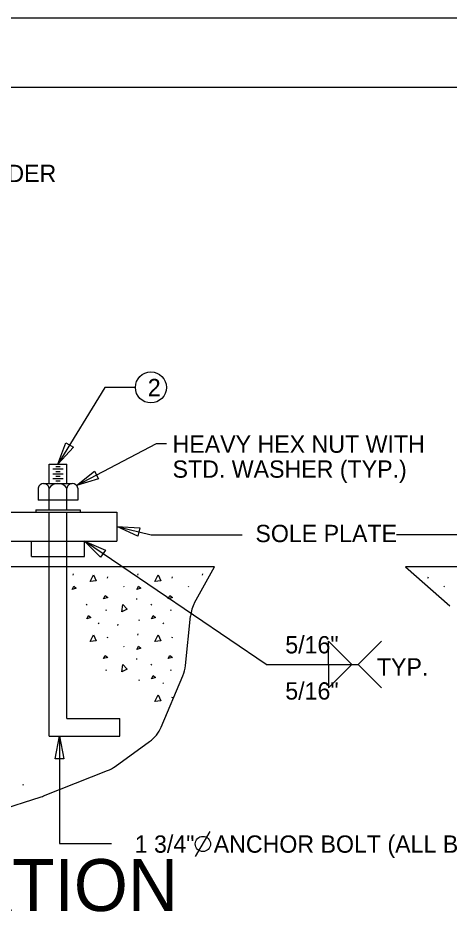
# Model space of a CAD drawing. Extents: x -125.5 to -89.4, y -5.1 to 16.9.
# Drawn here: x -115.57 to -112.46, y 10.36 to 16.93 of the extents above; entities that cross this region are included whole.
import ezdxf

# ---------------------------------------------------------------- set-up
doc = ezdxf.new("R2010")
doc.units = 0
for name, color, linetype in [('BR_AUTO DIMENSION', 7, 'Continuous'), ('BR_BORDER LINES', 7, 'Continuous'), ('BR_CONCRETE', 7, 'Continuous'), ('BR_REBAR', 7, 'Continuous'), ('BR_STRUCTURAL STEEL', 7, 'Continuous'), ('BR_TEXT', 7, 'Continuous'), ('Default', 7, 'Continuous'), ('Level 31', 7, 'Continuous')]:
    doc.layers.add(name, color=color, linetype=linetype)

msp = doc.modelspace()

# ---------------------------------------------------------------- linework, layer by layer
at = {"layer": 'BR_AUTO DIMENSION'}
for p, q in [((-114.9467, 14.269), (-115.2844, 13.7148)), ((-114.7256, 14.269), (-114.9467, 14.269)), ((-115.1496, 13.5602), (-114.5741, 13.864)), ((-114.5741, 13.864), (-114.5007, 13.864)), ((-114.8585, 13.2641), (-114.6122, 13.2038)), ((-113.7814, 12.2684), (-115.0933, 13.1599)), ((-114.6122, 13.2038), (-113.9558, 13.2038)), ((-112.0009, 13.2038), (-112.8408, 13.2038)), ((-113.1645, 12.2684), (-113.3326, 12.4365)), ((-113.3326, 12.2684), (-113.3326, 12.4365)), ((-112.9495, 12.4365), (-113.1176, 12.2684)), ((-113.7814, 12.2684), (-113.1176, 12.2684)), ((-113.1645, 12.2684), (-113.3326, 12.1003)), ((-113.3326, 12.2684), (-113.3326, 12.1003)), ((-113.1176, 12.2684), (-112.9495, 12.1003)), ((-115.2733, 11.7505), (-115.2733, 10.9757)), ((-115.2733, 10.9757), (-114.8991, 10.9757))]:
    msp.add_line(p, q, dxfattribs=at)
for points in [[(-115.1732, 13.8374), (-115.2844, 13.7148), (-115.2265, 13.8699)], [(-114.9913, 13.6085), (-115.1496, 13.5602), (-115.0204, 13.6637)], [(-114.7083, 13.1947), (-114.8585, 13.2641), (-114.6933, 13.2554)], [(-114.9764, 13.0427), (-115.0933, 13.1599), (-114.9413, 13.0944)], [(-115.3045, 11.588), (-115.2733, 11.7505), (-115.242, 11.588)]]:
    msp.add_lwpolyline(points, close=True, dxfattribs=at)
msp.add_circle((-114.6135, 14.269), 0.1121, dxfattribs=at)
at = {"layer": 'BR_BORDER LINES'}
msp.add_line((-90.0334, 16.4338), (-123.6994, 16.4338), dxfattribs=at)
at = {"layer": 'BR_CONCRETE'}
for p, q in [((-114.1549, 12.9727), (-119.7474, 12.9727)), ((-110.9149, 12.9727), (-112.7753, 12.9727))]:
    msp.add_line(p, q, dxfattribs=at)
at = {"layer": 'BR_REBAR'}
for p, q in [((-115.3481, 13.7148), (-115.2207, 13.7148)), ((-115.3481, 13.5762), (-115.3481, 13.7148)), ((-115.3226, 13.6802), (-115.2462, 13.6802)), ((-115.3003, 13.6975), (-115.2685, 13.6975)), ((-115.2207, 13.5762), (-115.2207, 13.7148)), ((-115.3226, 13.6455), (-115.2462, 13.6455)), ((-115.3226, 13.6109), (-115.2462, 13.6109)), ((-115.3003, 13.6628), (-115.2685, 13.6628)), ((-115.3003, 13.6282), (-115.2685, 13.6282)), ((-115.4277, 13.5415), (-115.4277, 13.4549)), ((-115.3879, 13.5762), (-115.1809, 13.5762)), ((-115.3481, 13.3855), (-115.3481, 13.5415)), ((-115.3003, 13.5935), (-115.2685, 13.5935)), ((-115.2207, 13.3855), (-115.2207, 13.5415)), ((-115.1411, 13.5415), (-115.1411, 13.4549)), ((-115.1411, 13.4549), (-115.4277, 13.4549)), ((-115.4436, 13.3855), (-115.4436, 13.3682)), ((-115.4436, 13.3855), (-115.1251, 13.3855)), ((-115.4436, 13.3682), (-115.1251, 13.3682)), ((-115.3481, 13.1599), (-115.3481, 13.3682)), ((-115.2207, 13.1599), (-115.2207, 13.3682)), ((-115.1251, 13.3855), (-115.1251, 13.3682)), ((-115.3481, 12.9727), (-115.3481, 13.1599)), ((-115.2207, 12.9727), (-115.2207, 13.1599)), ((-115.3481, 11.7505), (-115.3481, 12.9727)), ((-115.2207, 11.8779), (-115.2207, 12.9727)), ((-115.2207, 11.8779), (-114.8388, 11.8779)), ((-114.8388, 11.7505), (-114.8388, 11.8779)), ((-115.3481, 11.7505), (-114.8388, 11.7505))]:
    msp.add_line(p, q, dxfattribs=at)
for centre, major_axis, start_param, end_param in [((-115.3879, 13.5318), (0, 0.0444), 4.933703, 7.632667), ((-115.2844, 13.4895), (0, 0.0867), 5.35589, 7.210481), ((-115.1809, 13.5318), (0, 0.0444), 4.933703, 7.632667)]:
    msp.add_ellipse(centre, major_axis=major_axis, ratio=0.918783, start_param=start_param, end_param=end_param, dxfattribs=at)
at = {"layer": 'BR_STRUCTURAL STEEL'}
for p, q in [((-118.1036, 13.3682), (-114.8585, 13.3682)), ((-114.8585, 13.3682), (-114.8585, 13.1599)), ((-118.1036, 13.1599), (-114.8585, 13.1599)), ((-115.4755, 13.0491), (-115.4755, 13.1599)), ((-115.0933, 13.0491), (-115.0933, 13.1599)), ((-115.4755, 13.0491), (-115.0933, 13.0491))]:
    msp.add_line(p, q, dxfattribs=at)
at = {"layer": 'BR_TEXT'}
msp.add_line((-114.2907, 10.8823), (-114.1857, 11.0642), dxfattribs=at)
msp.add_circle((-114.2382, 10.9732), 0.055, dxfattribs=at)
at = {"layer": 'Default'}
for p, q in [((-114.2979, 12.7146), (-114.1549, 12.9727)), ((-112.7753, 12.9727), (-112.4566, 12.6913)), ((-115.1751, 12.9144), (-115.1714, 12.9227)), ((-114.9277, 12.8931), (-114.924, 12.9014)), ((-114.7084, 12.9144), (-114.7047, 12.9227)), ((-114.461, 12.8931), (-114.4573, 12.9014)), ((-114.2418, 12.9144), (-114.2381, 12.9227)), ((-112.6148, 12.8931), (-112.6111, 12.9014)), ((-114.812, 12.8339), (-114.8083, 12.8283)), ((-114.3454, 12.8339), (-114.3417, 12.8283)), ((-112.4991, 12.8339), (-112.4954, 12.8283)), ((-115.0775, 12.6961), (-115.0738, 12.7044)), ((-114.7185, 12.7452), (-114.7176, 12.7368)), ((-114.6109, 12.6961), (-114.6072, 12.7044)), ((-114.9369, 12.6581), (-114.9332, 12.6665)), ((-114.4703, 12.6581), (-114.4666, 12.6665)), ((-114.9935, 12.5689), (-114.9898, 12.5634)), ((-114.8528, 12.5508), (-114.849, 12.5592)), ((-114.7014, 12.5925), (-114.6977, 12.5869)), ((-114.5268, 12.5689), (-114.5231, 12.5634)), ((-114.3637, 12.2606), (-114.3279, 12.6183)), ((-114.7084, 12.4815), (-114.7047, 12.4898)), ((-114.9277, 12.4602), (-114.924, 12.4686)), ((-114.461, 12.4602), (-114.4573, 12.4686)), ((-114.812, 12.401), (-114.8083, 12.3955)), ((-114.7185, 12.3123), (-114.7176, 12.304)), ((-114.9369, 12.2253), (-114.9332, 12.2336)), ((-114.6109, 12.2632), (-114.6072, 12.2715)), ((-114.4703, 12.2253), (-114.4666, 12.2336)), ((-114.5396, 11.8175), (-114.3824, 12.1877)), ((-114.7014, 12.1596), (-114.6977, 12.1541)), ((-114.5268, 12.1361), (-114.5231, 12.1305)), ((-114.461, 12.0274), (-114.4573, 12.0357)), ((-114.8713, 11.533), (-114.6231, 11.7128)), ((-115.3892, 11.3199), (-114.926, 11.503)), ((-115.5367, 11.3975), (-115.533, 11.4059)), ((-116.1074, 11.0907), (-115.4053, 11.3142))]:
    msp.add_line(p, q, dxfattribs=at)
for points in [[(-115.0526, 12.8681), (-115.0276, 12.9153), (-115.0081, 12.8718), (-115.0516, 12.8681)], [(-114.5859, 12.8681), (-114.5609, 12.9153), (-114.5415, 12.8718), (-114.585, 12.8681)], [(-115.1816, 12.8098), (-115.1705, 12.833), (-115.152, 12.8191), (-115.1816, 12.8098)], [(-114.7149, 12.8098), (-114.7038, 12.833), (-114.6853, 12.8191), (-114.7149, 12.8098)], [(-114.9552, 12.7437), (-114.9441, 12.7668), (-114.9256, 12.753), (-114.9552, 12.7437)], [(-114.4886, 12.7437), (-114.4775, 12.7668), (-114.459, 12.753), (-114.4886, 12.7437)], [(-114.8244, 12.6486), (-114.8171, 12.7014), (-114.7839, 12.6672), (-114.8235, 12.6489)], [(-115.0757, 12.5989), (-115.0646, 12.6221), (-115.0461, 12.6082), (-115.0757, 12.5989)], [(-114.609, 12.5989), (-114.5979, 12.6221), (-114.5794, 12.6082), (-114.609, 12.5989)], [(-115.0526, 12.4353), (-115.0276, 12.4824), (-115.0081, 12.439), (-115.0516, 12.4353)], [(-114.5859, 12.4353), (-114.5609, 12.4824), (-114.5415, 12.439), (-114.585, 12.4353)], [(-114.7149, 12.377), (-114.7038, 12.4001), (-114.6853, 12.3862), (-114.7149, 12.377)], [(-114.9552, 12.3109), (-114.9441, 12.334), (-114.9256, 12.3201), (-114.9552, 12.3109)], [(-114.4886, 12.3109), (-114.4775, 12.334), (-114.459, 12.3201), (-114.4886, 12.3109)], [(-114.8244, 12.2157), (-114.8171, 12.2686), (-114.7839, 12.2344), (-114.8235, 12.216)], [(-114.609, 12.1661), (-114.5979, 12.1892), (-114.5794, 12.1753), (-114.609, 12.1661)], [(-114.5859, 12.0024), (-114.5609, 12.0496), (-114.5415, 12.0061), (-114.585, 12.0024)]]:
    msp.add_lwpolyline(points, dxfattribs=at)
for centre, start, end in [((-114.0792, 12.5934), 151.01619, 174.28906), ((-114.6125, 12.2855), 336.98375, 354.28906), ((-114.7697, 11.9153), 305.91455, 336.98375), ((-115.0179, 11.7355), 291.57303, 305.91455), ((-115.4811, 11.5524), 287.65574, 291.57303)]:
    msp.add_arc(centre, 0.25, start, end, dxfattribs=at)
at = {"layer": 'Level 31'}
msp.add_lwpolyline([(-125.5328, -5.0661), (-89.5328, -5.0661), (-89.5328, 16.9339), (-125.5328, 16.9339)], close=True, dxfattribs=at)

# ---------------------------------------------------------------- texts
at = {"layer": 'BR_AUTO DIMENSION'}
for s, p in [('L GIRDER', (-116.0864, 15.7511)), ('2', (-114.6361, 14.2054)), ('HEAVY HEX NUT WITH ', (-114.4574, 13.7969)), ('STD. WASHER (TYP.)', (-114.4574, 13.6168)), ('SOLE PLATE', (-113.8593, 13.152)), ('1 3/4"   ANCHOR BOLT (ALL BENTS)', (-114.7308, 10.91))]:
    msp.add_text(s, height=0.125, dxfattribs=at).set_placement(p)
at = {"layer": 'BR_TEXT'}
for s, height, p in [('5/16"', 0.125, (-113.6438, 12.3489)), ('TYP.', 0.125, (-112.9827, 12.1886)), ('5/16"', 0.125, (-113.6438, 12.0154)), ('END ELEVATION', 0.375, (-118.4304, 10.4891))]:
    msp.add_text(s, height=height, dxfattribs=at).set_placement(p)

doc.saveas('drawing.dxf')
